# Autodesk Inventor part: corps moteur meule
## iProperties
Shininess: 64.0
Length Units: 11269
Angle Units: 11279
Time Units: 11290
Mass Units: 11283
Length Display Precision: 3
Angle Display Precision: 2
Compacted: True
Part Number: corps moteur meule
Document SubType Name: Modeling
Created: 2005-01
Material: Par défaut
Designer: LEGERET Philippe
Density: 0.0
Volumn: 0.0
Area: 0.0
PropertySet Name: Model Information
Control State: 0
Master: False
Checked Out: False
Author: LEGERET Philippe
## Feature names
1. Extrusion1
2. Congé1 [Fillet]
3. Extrusion2
4. Extrusion3
5. Extrusion4
6. Chanfrein1 [Chamfer]
7. Extrusion5
8. Réseau circulaire1 [Circular Pattern]
9. Extrusion6
10. Extrusion7
11. Congé2 [Fillet]
